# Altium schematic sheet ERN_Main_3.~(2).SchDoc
size A; SheetNumber: 3; SheetTotal: 3; SPICEModelCacheXVWYUVSQ: <root> / <DocumentId>XVWYUVSQ</DocumentId> / <CacheFrame Number="0"> / <Model Name="irf1010" Kind="CKT"> / <Text>*IRF1010 MCE 4-2-96 / *55V  75A .014 ohm HEXFET pkg:TO-220 2,1,3 / .SUBCKT IRF1010  10 20 40 40 / M1   1  2  3  3  DMOS L=1U W=1U / RD  10  1  5.65M / RS  30  3  1.35M / RG  20  2  12.1 / CGS  2  3  2.15N / EGD 12  0  2  1  1 / VFB 14  0  0 / FFB  2  1  VFB  1 / CGD 13 14  4.49N / R1  13  0  1 / D1  12 13  DLIM / DDG 15 14  DCGD / R2  12 15  1 / D2  15  0  DLIM / DSD  3 10  DSUB / LS  30 40  7.5N / .MODEL DMOS NMOS (LEVEL=3 THETA=60M VMAX=114K ETA=2M VTO=3 KP=19.4) / .MODEL DCGD D (CJO=4.49N VJ=.6 M=.68) / .MODEL DSUB D (IS=311N N=1.5 RS=8.67M BV=55 CJO=4.08N VJ=.8 M=.42 TT=100N) / .MODEL DLIM D (IS=100U) / .ENDS IRF1010</Text> / </Model> / </CacheFrame> / </root>
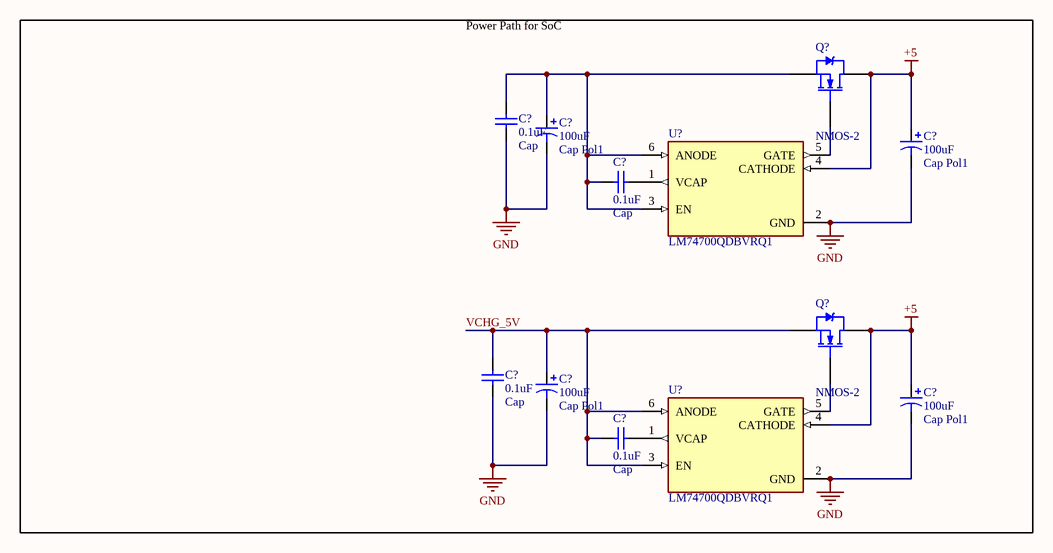
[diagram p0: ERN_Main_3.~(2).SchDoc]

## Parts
(Parts that share a designator on the sheet are numbered #1, #2 ... from top to bottom, then left to right.)
C?#1  Cap  value 0.1uF  [RAD-0.3]
C?#2  Cap Pol1  value 100uF  [RB7.6-15]
C?#3  Cap Pol1  value 100uF  [RB7.6-15]
C?#4  Cap  value 0.1uF  [RAD-0.3]
C?#5  Cap  value 0.1uF  [RAD-0.3]
C?#6  Cap Pol1  value 100uF  [RB7.6-15]
C?#7  Cap Pol1  value 100uF  [RB7.6-15]
C?#8  Cap  value 0.1uF  [RAD-0.3]
Q?#1  NMOS-2  [TO-220AB]
Q?#2  NMOS-2  [TO-220AB]
U?#1  LM74700QDBVRQ1  [SOT95P280X145-6N]
U?#2  LM74700QDBVRQ1  [SOT95P280X145-6N]

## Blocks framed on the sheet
Power Path for SoC: C?#1-C?#8 Q?#1 Q?#2 U?#1 U?#2

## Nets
+5: C?#3.1 C?#7.1 Q?#1.2(D) Q?#2.2(D) U?#1.4(CATHODE) U?#2.4(CATHODE)
GND: C?#1.1 C?#2.2 C?#3.2 C?#5.1 C?#6.2 C?#7.2 U?#1.2(GND) U?#2.2(GND)
VCHG_5V: C?#5.2 C?#6.1 C?#8.2 Q?#2.3(S) U?#2.3(EN) U?#2.6(ANODE)
NetC?#1_2: C?#1.2 C?#2.1 C?#4.2 Q?#1.3(S) U?#1.3(EN) U?#1.6(ANODE)
NetC?#4_1: C?#4.1 U?#1.1(VCAP)
NetC?#8_1: C?#8.1 U?#2.1(VCAP)
NetQ?#1_1: Q?#1.1(G) U?#1.5(GATE)
NetQ?#2_1: Q?#2.1(G) U?#2.5(GATE)

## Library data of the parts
C?#1 C?#4 C?#5 C?#8 = Cap: Capacitor
C?#2 C?#3 C?#6 C?#7 = Cap Pol1: Polarized Capacitor (Radial)
Q?#1 Q?#2 = NMOS-2: N-Channel Power MOSFET; Note: Pin 2 is electrically connected to pin 4.
U?#1 U?#2 = LM74700QDBVRQ1: 3.2-V to 65-V, 80-uA IQ automotive ideal diode controller; MF: Texas Instruments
